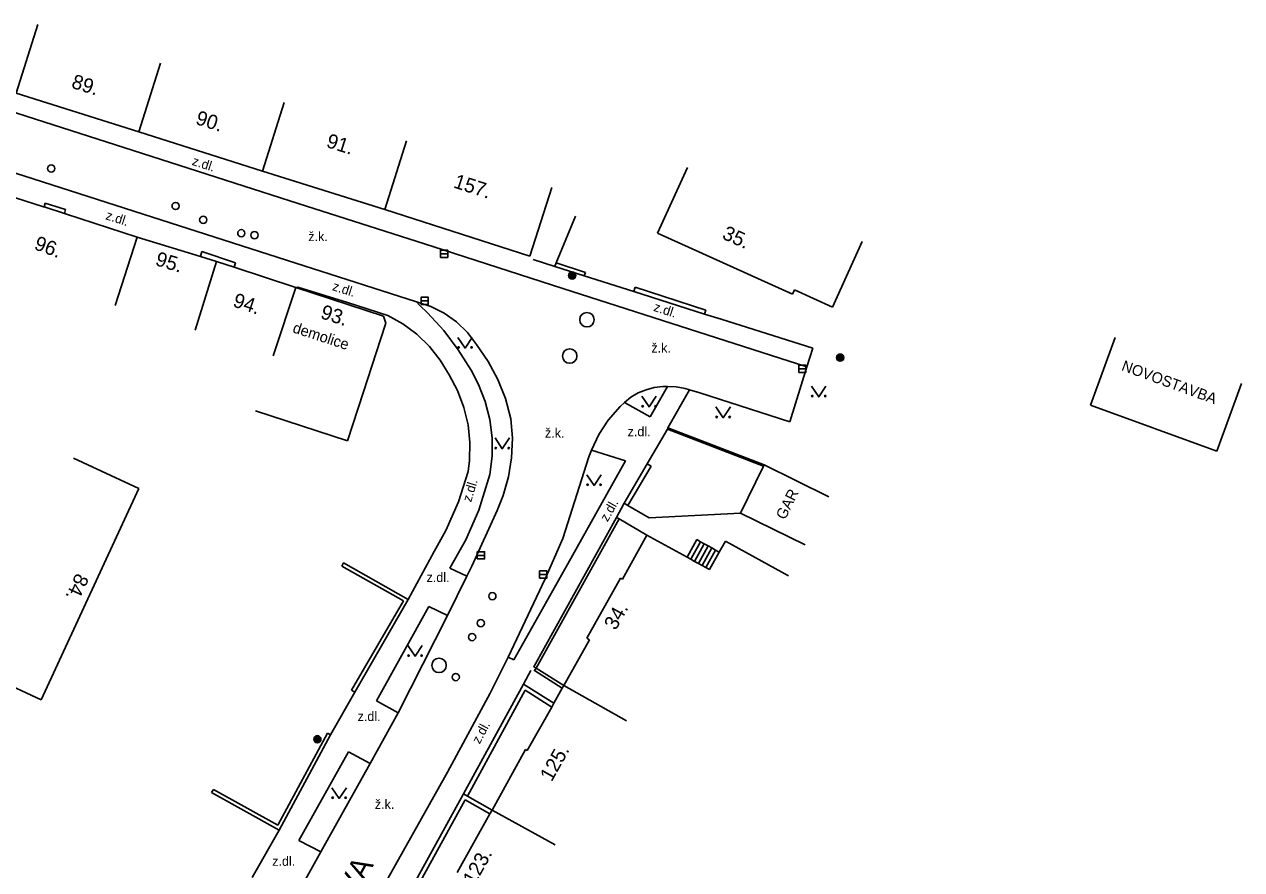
# Model space of a CAD drawing. Extents: x -538441 to -536770, y -1181008 to -1179809.
# Drawn here: x -537652.5 to -537568.1, y -1180541.9 to -1180483.2 of the extents above; entities that cross this region are included whole.
import ezdxf

# ---------------------------------------------------------------- set-up
doc = ezdxf.new("R2010")
doc.units = 0
for name, color, linetype in [('Vrstva 10', 7, 'Continuous'), ('Vrstva 11', 7, 'Continuous'), ('Vrstva 25', 7, 'Continuous'), ('Vrstva 27', 7, 'Continuous'), ('Vrstva 28', 7, 'Continuous'), ('Vrstva 36', 7, 'Continuous'), ('Vrstva 40', 7, 'Continuous'), ('Vrstva 41', 7, 'Continuous'), ('Vrstva 42', 7, 'Continuous'), ('Vrstva 47', 7, 'Continuous'), ('Vrstva 49', 7, 'Continuous'), ('Vrstva 5', 7, 'Continuous'), ('Vrstva 7', 7, 'Continuous'), ('Vrstva 8', 7, 'Continuous')]:
    doc.layers.add(name, color=color, linetype=linetype)

msp = doc.modelspace()

# ---------------------------------------------------------------- linework, layer by layer
at = {"layer": 'Vrstva 10'}
for p, q in [((-537644.968, -1180491.991), (-537653.629, -1180489.216)), ((-537658.605, -1180491.8), (-537644.277, -1180496.402)), ((-537634.095, -1180495.471), (-537644.968, -1180491.991)), ((-537624.169, -1180498.65), (-537634.095, -1180495.471)), ((-537644.277, -1180496.402), (-537633.097, -1180499.981)), ((-537615.159, -1180501.552), (-537624.169, -1180498.65)), ((-537633.097, -1180499.981), (-537625.32, -1180502.484)), ((-537604.502, -1180504.988), (-537615.159, -1180501.552)), ((-537598.222, -1180506.988), (-537604.502, -1180504.988)), ((-537599.418, -1180510.818), (-537598.222, -1180506.988)), ((-537606.375, -1180508.585), (-537605.658, -1180508.805)), ((-537605.658, -1180508.805), (-537599.418, -1180510.818)), ((-537615.158, -1180518.911), (-537613.359, -1180513.242)), ((-537613.359, -1180513.242), (-537613.182, -1180512.785)), ((-537616.376, -1180521.7), (-537615.158, -1180518.911)), ((-537621.821, -1180521.513), (-537623.163, -1180524.264)), ((-537618.955, -1180527.156), (-537616.376, -1180521.7)), ((-537623.163, -1180524.264), (-537626.588, -1180531.018)), ((-537620.2, -1180529.637), (-537618.955, -1180527.156)), ((-537623.15, -1180535.129), (-537620.2, -1180529.637)), ((-537626.588, -1180531.018), (-537628.528, -1180534.519)), ((-537628.528, -1180534.519), (-537631.96, -1180540.657)), ((-537628.546, -1180544.722), (-537623.15, -1180535.129)), ((-537631.96, -1180540.657), (-537633.898, -1180544.141))]:
    msp.add_line(p, q, dxfattribs=at)
for points in [[(-537625.32, -1180502.484), (-537624.321, -1180502.806), (-537623.383, -1180503.277), (-537622.528, -1180503.884), (-537621.774, -1180504.614), (-537621.142, -1180505.447)], [(-537621.142, -1180505.447), (-537620.337, -1180506.619), (-537619.669, -1180507.873), (-537619.145, -1180509.195), (-537618.764, -1180510.614)], [(-537610.892, -1180509.474), (-537610.431, -1180509.11), (-537609.924, -1180508.813), (-537609.382, -1180508.587), (-537608.814, -1180508.436), (-537608.231, -1180508.365), (-537607.907, -1180508.359)], [(-537607.907, -1180508.359), (-537607.29, -1180508.389), (-537606.683, -1180508.498), (-537606.375, -1180508.585)], [(-537613.182, -1180512.785), (-537612.651, -1180511.691), (-537612.004, -1180510.705), (-537611.185, -1180509.757), (-537610.892, -1180509.474)], [(-537618.764, -1180510.614), (-537618.657, -1180511.957), (-537618.71, -1180513.303), (-537618.922, -1180514.633), (-537619.291, -1180515.929), (-537619.715, -1180516.973)], [(-537619.715, -1180516.973), (-537621.478, -1180520.825), (-537621.821, -1180521.513)]]:
    msp.add_lwpolyline(points, dxfattribs=at)
at = {"layer": 'Vrstva 11'}
for p, q in [((-537651.153, -1180495.905), (-537651.069, -1180495.645)), ((-537649.657, -1180496.086), (-537651.069, -1180495.645)), ((-537649.745, -1180496.359), (-537649.657, -1180496.086)), ((-537640.308, -1180499.337), (-537640.201, -1180498.99)), ((-537637.869, -1180499.79), (-537640.201, -1180498.99)), ((-537637.965, -1180500.083), (-537637.869, -1180499.79)), ((-537633.552, -1180501.461), (-537633.69, -1180501.49)), ((-537633.552, -1180501.461), (-537630.101, -1180502.543)), ((-537630.101, -1180502.543), (-537627.307, -1180503.435)), ((-537625.092, -1180502.753), (-537625.32, -1180502.484)), ((-537597.812, -1180505.702), (-537604.18, -1180503.69)), ((-537598.222, -1180506.988), (-537597.812, -1180505.702)), ((-537609.11, -1180510.478), (-537607.907, -1180508.359)), ((-537606.375, -1180508.585), (-537607.87, -1180511.24)), ((-537610.892, -1180509.474), (-537609.11, -1180510.478)), ((-537614.807, -1180520.662), (-537610.803, -1180513.518)), ((-537610.803, -1180513.518), (-537613.182, -1180512.785)), ((-537609.33, -1180518.67), (-537611.257, -1180517.551)), ((-537609.171, -1180517.466), (-537602.83, -1180517.15)), ((-537606.541, -1180520.207), (-537605.87, -1180518.99)), ((-537606.279, -1180520.352), (-537605.607, -1180519.134)), ((-537606.016, -1180520.497), (-537605.344, -1180519.28)), ((-537605.753, -1180520.642), (-537605.082, -1180519.425)), ((-537624.089, -1180519.81), (-537625.88, -1180523.14)), ((-537605.49, -1180520.786), (-537604.819, -1180519.569)), ((-537605.227, -1180520.931), (-537604.556, -1180519.714)), ((-537621.821, -1180521.513), (-537623.003, -1180520.976)), ((-537618.559, -1180527.34), (-537614.807, -1180520.662)), ((-537628.097, -1180530.179), (-537624.465, -1180523.627)), ((-537624.465, -1180523.627), (-537623.163, -1180524.264)), ((-537618.955, -1180527.156), (-537618.559, -1180527.34)), ((-537626.588, -1180531.018), (-537628.097, -1180530.179)), ((-537633.472, -1180539.873), (-537630.041, -1180533.715)), ((-537630.041, -1180533.715), (-537628.528, -1180534.519)), ((-537631.96, -1180540.657), (-537633.472, -1180539.873))]:
    msp.add_line(p, q, dxfattribs=at)
for points in [[(-537621.53, -1180507.23), (-537622.411, -1180505.81), (-537623.423, -1180504.482), (-537624.558, -1180503.256), (-537625.092, -1180502.753)], [(-537627.307, -1180503.435), (-537626.249, -1180504.022), (-537625.278, -1180504.743), (-537624.41, -1180505.586), (-537623.661, -1180506.536), (-537623.055, -1180507.554)], [(-537623.055, -1180507.554), (-537622.468, -1180508.649), (-537622.026, -1180509.811), (-537621.736, -1180511.019), (-537621.604, -1180512.255), (-537621.632, -1180513.498), (-537621.731, -1180514.27)], [(-537620.234, -1180514.46), (-537620.071, -1180513.193), (-537620.068, -1180511.915), (-537620.224, -1180510.646), (-537620.537, -1180509.407), (-537621.003, -1180508.217), (-537621.53, -1180507.23)], [(-537621.731, -1180514.27), (-537622.392, -1180516.36), (-537623.278, -1180518.366), (-537624.089, -1180519.81)], [(-537623.003, -1180520.976), (-537621.888, -1180519.01), (-537620.989, -1180516.937), (-537620.313, -1180514.781), (-537620.234, -1180514.46)], [(-537604.302, -1180519.855), (-537604.556, -1180519.714), (-537604.819, -1180519.569), (-537605.082, -1180519.425), (-537605.344, -1180519.28), (-537605.607, -1180519.134), (-537605.87, -1180518.99)]]:
    msp.add_lwpolyline(points, dxfattribs=at)
at = {"layer": 'Vrstva 25'}
for centre, radius in [((-537614.51, -1180500.66), 0.25), ((-537614.51, -1180500.66), 0.2), ((-537614.51, -1180500.66), 0.15), ((-537614.51, -1180500.66), 0.1), ((-537614.51, -1180500.66), 0.05), ((-537595.92, -1180506.36), 0.25), ((-537595.92, -1180506.36), 0.2), ((-537595.92, -1180506.36), 0.15), ((-537595.92, -1180506.36), 0.1), ((-537595.92, -1180506.36), 0.05), ((-537632.19, -1180532.84), 0.25), ((-537632.19, -1180532.84), 0.2), ((-537632.19, -1180532.84), 0.15), ((-537632.19, -1180532.84), 0.1), ((-537632.19, -1180532.84), 0.05)]:
    msp.add_circle(centre, radius, dxfattribs=at)
at = {"layer": 'Vrstva 27'}
for p, q in [((-537623.649, -1180499.151), (-537623.149, -1180499.151)), ((-537624.991, -1180502.418), (-537624.491, -1180502.418)), ((-537598.796, -1180507.14), (-537598.296, -1180507.14)), ((-537621.094, -1180520.08), (-537620.594, -1180520.08)), ((-537616.767, -1180521.407), (-537616.267, -1180521.407))]:
    msp.add_line(p, q, dxfattribs=at)
for points in [[(-537623.649, -1180499.401), (-537623.149, -1180499.401), (-537623.149, -1180498.901), (-537623.649, -1180498.901)], [(-537624.991, -1180502.668), (-537624.491, -1180502.668), (-537624.491, -1180502.168), (-537624.991, -1180502.168)], [(-537598.796, -1180507.39), (-537598.296, -1180507.39), (-537598.296, -1180506.89), (-537598.796, -1180506.89)], [(-537621.094, -1180520.33), (-537620.594, -1180520.33), (-537620.594, -1180519.83), (-537621.094, -1180519.83)], [(-537616.767, -1180521.657), (-537616.267, -1180521.657), (-537616.267, -1180521.157), (-537616.767, -1180521.157)]]:
    msp.add_lwpolyline(points, close=True, dxfattribs=at)
for centre in [(-537613.488, -1180503.729), (-537614.681, -1180506.249), (-537623.746, -1180527.714)]:
    msp.add_circle(centre, 0.5, dxfattribs=at)
at = {"layer": 'Vrstva 28'}
for centre in [(-537650.655, -1180493.236), (-537642.022, -1180495.839), (-537640.109, -1180496.801), (-537637.469, -1180497.727), (-537636.553, -1180497.865), (-537620.049, -1180522.914), (-537620.853, -1180524.784), (-537621.455, -1180525.751), (-537622.587, -1180528.528)]:
    msp.add_circle(centre, 0.25, dxfattribs=at)
at = {"layer": 'Vrstva 36'}
for points in [[(-537622.444, -1180504.953), (-537621.944, -1180505.703), (-537621.444, -1180504.953)], [(-537597.904, -1180508.332), (-537597.404, -1180509.082), (-537596.904, -1180508.332)], [(-537609.673, -1180509.035), (-537609.173, -1180509.785), (-537608.673, -1180509.035)], [(-537604.535, -1180509.782), (-537604.035, -1180510.532), (-537603.535, -1180509.782)], [(-537619.862, -1180511.935), (-537619.362, -1180512.685), (-537618.862, -1180511.935)], [(-537613.494, -1180514.483), (-537612.994, -1180515.233), (-537612.494, -1180514.483)], [(-537625.911, -1180526.333), (-537625.411, -1180527.083), (-537624.911, -1180526.333)], [(-537631.178, -1180536.202), (-537630.678, -1180536.952), (-537630.178, -1180536.202)]]:
    msp.add_lwpolyline(points, dxfattribs=at)
for centre in [(-537622.394, -1180505.653), (-537621.495, -1180505.653), (-537597.854, -1180509.032), (-537596.955, -1180509.032), (-537609.623, -1180509.735), (-537608.724, -1180509.735), (-537604.485, -1180510.482), (-537603.586, -1180510.482), (-537619.812, -1180512.635), (-537618.913, -1180512.635), (-537613.444, -1180515.183), (-537612.545, -1180515.183), (-537625.861, -1180527.033), (-537624.962, -1180527.033), (-537631.128, -1180536.902), (-537630.229, -1180536.902)]:
    msp.add_circle(centre, 0.05, dxfattribs=at)
at = {"layer": 'Vrstva 5'}
for p, q in [((-537651.583, -1180483.233), (-537653.09, -1180488)), ((-537643.073, -1180485.923), (-537644.58, -1180490.69)), ((-537644.58, -1180490.69), (-537653.09, -1180488)), ((-537634.494, -1180488.659), (-537635.99, -1180493.43)), ((-537644.58, -1180490.69), (-537635.99, -1180493.43)), ((-537626.014, -1180491.319), (-537627.51, -1180496.09)), ((-537606.521, -1180493.174), (-537608.58, -1180497.73)), ((-537635.99, -1180493.43), (-537627.51, -1180496.09)), ((-537656.25, -1180494.26), (-537651.187, -1180495.894)), ((-537615.923, -1180494.555), (-537617.45, -1180499.316)), ((-537649.658, -1180496.387), (-537644.69, -1180497.99)), ((-537617.45, -1180499.316), (-537627.51, -1180496.09)), ((-537646.225, -1180502.748), (-537644.69, -1180497.99)), ((-537608.58, -1180497.73), (-537599.22, -1180501.96)), ((-537594.401, -1180498.294), (-537596.46, -1180502.85)), ((-537640.659, -1180504.459), (-537639.19, -1180499.68)), ((-537635.253, -1180506.239), (-537633.69, -1180501.49)), ((-537633.69, -1180501.49), (-537627.59, -1180503.48)), ((-537599.086, -1180501.663), (-537599.22, -1180501.96)), ((-537599.086, -1180501.663), (-537596.46, -1180502.85)), ((-537627.812, -1180505.109), (-537627.44, -1180503.97)), ((-537627.59, -1180503.48), (-537627.44, -1180503.97)), ((-537576.843, -1180504.954), (-537578.56, -1180509.65)), ((-537628.991, -1180508.723), (-537627.812, -1180505.109)), ((-537568.063, -1180508.164), (-537569.78, -1180512.86)), ((-537630.102, -1180512.127), (-537628.991, -1180508.723)), ((-537636.481, -1180510.046), (-537630.102, -1180512.127)), ((-537578.56, -1180509.65), (-537569.78, -1180512.86)), ((-537649.11, -1180513.338), (-537644.571, -1180515.434)), ((-537601.234, -1180513.9), (-537602.83, -1180517.15)), ((-537601.19, -1180513.81), (-537601.234, -1180513.9)), ((-537596.702, -1180516.014), (-537601.19, -1180513.81)), ((-537644.571, -1180515.434), (-537651.348, -1180530.109)), ((-537598.342, -1180519.354), (-537602.83, -1180517.15)), ((-537611.019, -1180521.733), (-537609.33, -1180518.67)), ((-537606.541, -1180520.207), (-537609.33, -1180518.67)), ((-537604.302, -1180519.855), (-537603.88, -1180519.09)), ((-537599.502, -1180521.505), (-537603.88, -1180519.09)), ((-537606.279, -1180520.352), (-537606.541, -1180520.207)), ((-537604.973, -1180521.072), (-537604.302, -1180519.855)), ((-537606.016, -1180520.497), (-537606.279, -1180520.352)), ((-537605.753, -1180520.642), (-537606.016, -1180520.497)), ((-537605.49, -1180520.786), (-537605.753, -1180520.642)), ((-537605.227, -1180520.931), (-537605.49, -1180520.786)), ((-537604.973, -1180521.072), (-537605.227, -1180520.931)), ((-537611.15, -1180521.66), (-537613.49, -1180525.83)), ((-537611.019, -1180521.733), (-537611.15, -1180521.66)), ((-537613.31, -1180525.931), (-537615.1, -1180529.12)), ((-537613.31, -1180525.931), (-537613.49, -1180525.83)), ((-537655.887, -1180528.013), (-537651.348, -1180530.109)), ((-537615.786, -1180530.345), (-537615.198, -1180529.295)), ((-537615.198, -1180529.295), (-537615.1, -1180529.12)), ((-537610.74, -1180531.567), (-537615.1, -1180529.12)), ((-537615.933, -1180530.607), (-537615.786, -1180530.345)), ((-537617.628, -1180533.632), (-537615.933, -1180530.607)), ((-537617.76, -1180533.56), (-537620.07, -1180537.76)), ((-537617.628, -1180533.632), (-537617.76, -1180533.56)), ((-537620.216, -1180538.022), (-537622.48, -1180542.09)), ((-537620.07, -1180537.76), (-537620.216, -1180538.022)), ((-537615.689, -1180540.17), (-537620.07, -1180537.76))]:
    msp.add_line(p, q, dxfattribs=at)
for points in [[(-537651.187, -1180495.894), (-537651.153, -1180495.905), (-537649.745, -1180496.359), (-537649.658, -1180496.387)], [(-537644.69, -1180497.99), (-537640.308, -1180499.337), (-537639.19, -1180499.68)], [(-537639.19, -1180499.68), (-537637.965, -1180500.083), (-537633.69, -1180501.49)]]:
    msp.add_lwpolyline(points, dxfattribs=at)
at = {"layer": 'Vrstva 7'}
for p, q in [((-537615.624, -1180499.787), (-537614.282, -1180496.549)), ((-537615.624, -1180499.787), (-537613.592, -1180500.452)), ((-537605.228, -1180503.065), (-537610.148, -1180501.475)), ((-537607.87, -1180511.24), (-537607.906, -1180511.333)), ((-537607.906, -1180511.333), (-537601.234, -1180513.9)), ((-537601.19, -1180513.81), (-537607.87, -1180511.24)), ((-537610.641, -1180516.612), (-537609.041, -1180513.882)), ((-537609.171, -1180517.466), (-537610.641, -1180516.612)), ((-537617.01, -1180527.917), (-537611.257, -1180517.551)), ((-537630.491, -1180520.821), (-537626.223, -1180523.233)), ((-537626.223, -1180523.233), (-537629.816, -1180529.445)), ((-537615.1, -1180529.12), (-537617.01, -1180527.917)), ((-537617.89, -1180529.02), (-537622.04, -1180536.63)), ((-537621.78, -1180536.779), (-537617.78, -1180529.444)), ((-537615.786, -1180530.345), (-537617.89, -1180529.02)), ((-537615.933, -1180530.607), (-537617.78, -1180529.444)), ((-537631.49, -1180532.421), (-537634.94, -1180538.808)), ((-537634.94, -1180538.808), (-537639.406, -1180536.321)), ((-537622.04, -1180536.63), (-537626.2, -1180544.17)), ((-537625.796, -1180544.059), (-537621.925, -1180537.042)), ((-537620.216, -1180538.022), (-537621.925, -1180537.042))]:
    msp.add_line(p, q, dxfattribs=at)
for points in [[(-537615.624, -1180499.787), (-537615.706, -1180500.028), (-537613.67, -1180500.69), (-537613.592, -1180500.452)], [(-537605.228, -1180503.065), (-537605.32, -1180503.35), (-537610.24, -1180501.76), (-537610.148, -1180501.475)], [(-537609.041, -1180513.882), (-537609.3, -1180513.73), (-537610.9, -1180516.46), (-537610.641, -1180516.612)], [(-537611.257, -1180517.551), (-537611.43, -1180517.45), (-537617.18, -1180527.81), (-537617.01, -1180527.917)], [(-537625.88, -1180523.14), (-537630.368, -1180520.603), (-537630.491, -1180520.821)], [(-537629.6, -1180529.57), (-537625.88, -1180523.14)], [(-537615.198, -1180529.295), (-537617.129, -1180528.079), (-537617.01, -1180527.917)], [(-537629.816, -1180529.445), (-537629.6, -1180529.57)], [(-537631.27, -1180532.54), (-537634.84, -1180539.15)], [(-537631.49, -1180532.421), (-537631.27, -1180532.54)], [(-537639.528, -1180536.539), (-537639.406, -1180536.321)], [(-537634.84, -1180539.15), (-537639.528, -1180536.539)], [(-537620.07, -1180537.76), (-537621.78, -1180536.779), (-537622.04, -1180536.63)]]:
    msp.add_lwpolyline(points, dxfattribs=at)
at = {"layer": 'Vrstva 8'}
for p, q in [((-537617.21, -1180499.55), (-537615.706, -1180500.028)), ((-537613.67, -1180500.69), (-537610.24, -1180501.76)), ((-537605.32, -1180503.35), (-537604.18, -1180503.69)), ((-537607.906, -1180511.333), (-537609.3, -1180513.73)), ((-537610.9, -1180516.46), (-537611.43, -1180517.45)), ((-537617.37, -1180528.07), (-537617.89, -1180529.02)), ((-537631.27, -1180532.54), (-537629.6, -1180529.57)), ((-537636.72, -1180542.44), (-537634.84, -1180539.15))]:
    msp.add_line(p, q, dxfattribs=at)

# ---------------------------------------------------------------- texts
at = {"layer": 'Vrstva 40'}
for rotation, p in [(342.25227, (-537640.933, -1180492.977)), (342.19354, (-537646.927, -1180496.749)), (342.15941, (-537631.201, -1180501.666)), (342.12978, (-537608.913, -1180503.105)), (73.08069, (-537621.522, -1180516.424)), (60.73066, (-537612.055, -1180517.793)), (61.78648, (-537620.932, -1180533.209))]:
    msp.add_text('z.dl.', height=0.65, rotation=rotation, dxfattribs=at).set_placement(p)
for s, p in [('ž.k.', (-537632.818, -1180498.276)), ('ž.k.', (-537609.015, -1180506.009)), ('ž.k.', (-537616.399, -1180511.913)), ('z.dl.', (-537610.663, -1180511.811)), ('z.dl.', (-537624.615, -1180521.929)), ('z.dl.', (-537629.397, -1180531.575)), ('ž.k.', (-537628.203, -1180537.678)), ('z.dl.', (-537635.321, -1180541.623))]:
    msp.add_text(s, height=0.65, dxfattribs=at).set_placement(p)
at = {"layer": 'Vrstva 41'}
for s, rotation, p in [('NOVOSTAVBA', 339.9174, (-537576.453, -1180507.226)), ('GAR', 63.84813, (-537599.739, -1180517.662))]:
    msp.add_text(s, height=0.75, rotation=rotation, dxfattribs=at).set_placement(p)
at = {"layer": 'Vrstva 42'}
msp.add_text('demolice', height=0.75, rotation=341.93214, dxfattribs=at).set_placement((-537633.959, -1180504.594))
at = {"layer": 'Vrstva 47'}
for s, rotation, p in [('89.', 342.45832, (-537649.317, -1180487.62)), ('90.', 342.37539, (-537640.699, -1180490.139)), ('91.', 342.58444, (-537631.63, -1180491.736)), ('157.', 342.09025, (-537622.803, -1180494.543)), ('35.', 335.68069, (-537604.171, -1180498.076)), ('96.', 339.74557, (-537651.906, -1180498.819)), ('95.', 342.91923, (-537643.493, -1180499.931)), ('94.', 341.78409, (-537638.114, -1180502.794)), ('93.', 341.93214, (-537632.037, -1180503.607)), ('84.', 245.21223, (-537648.913, -1180521.257)), ('34.', 60.70099, (-537611.49, -1180525.331)), ('125.', 60.7388, (-537615.935, -1180535.837)), ('123.', 60.90048, (-537621.285, -1180543.026))]:
    msp.add_text(s, height=1, rotation=rotation, dxfattribs=at).set_placement(p)
at = {"layer": 'Vrstva 49'}
msp.add_text('ul. MAZURKOVA', height=1.5, rotation=60.89426, dxfattribs=at).set_placement((-537635.731, -1180554.98))

doc.saveas('drawing.dxf')
